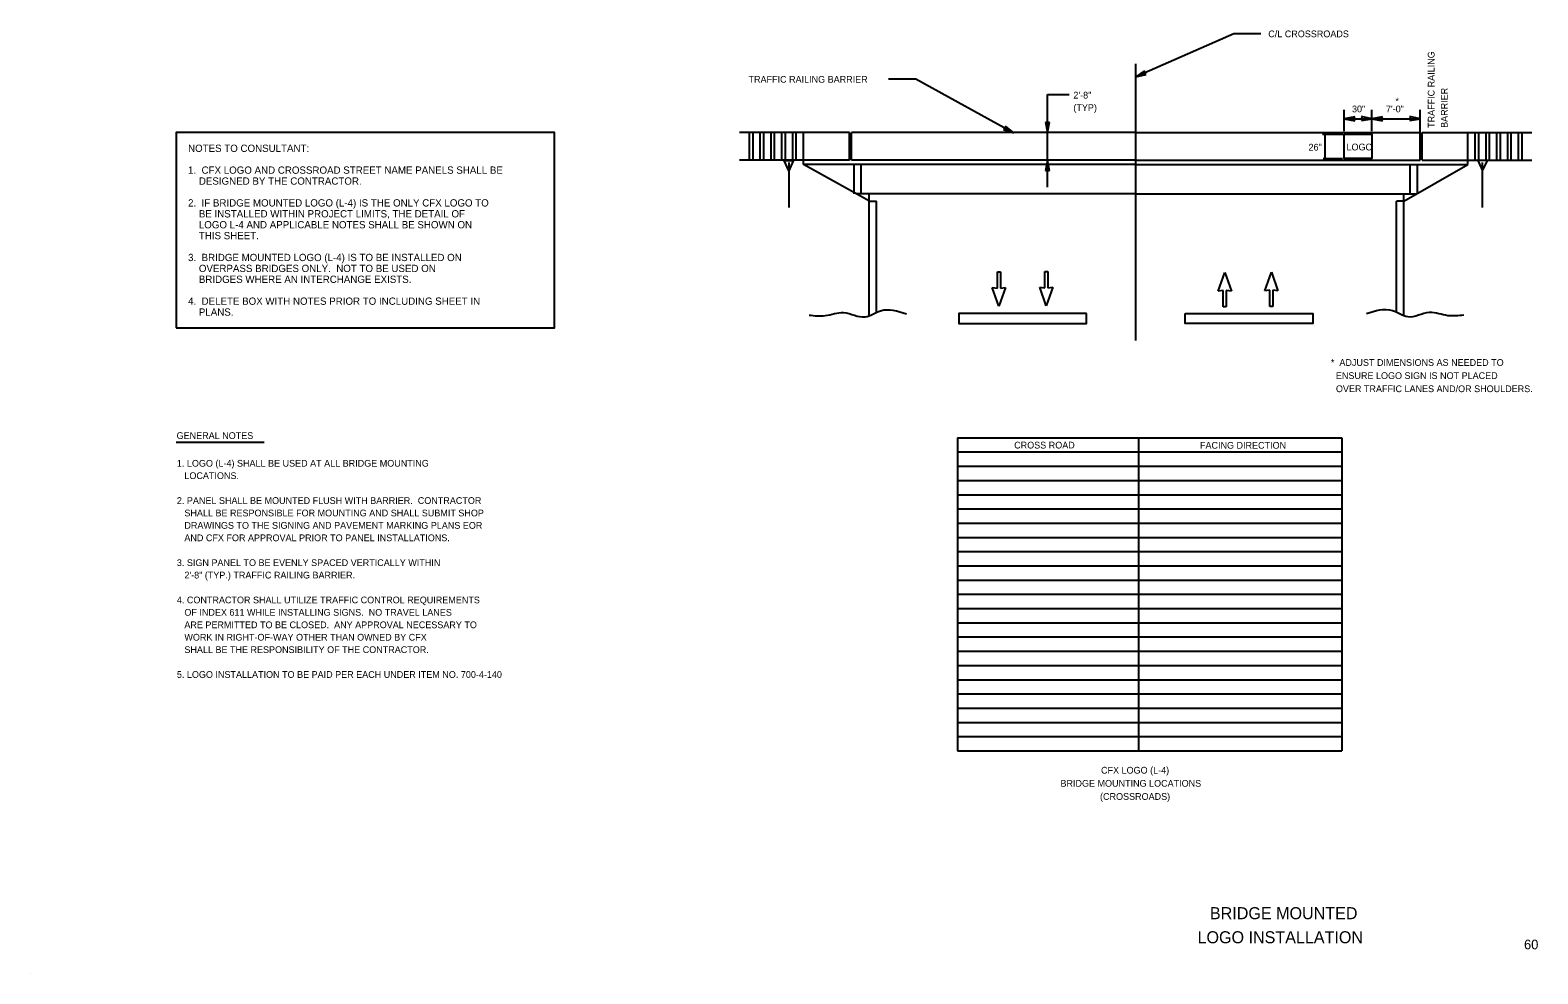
# Model space of a CAD drawing. Extents: x 53062 to 53689, y 9298 to 9690.
import ezdxf

# ---------------------------------------------------------------- set-up
doc = ezdxf.new("R2010")
doc.units = 0
for name, color, linetype in [('AdhocPoint_dp', 7, 'Continuous'), ('Bridge', 7, 'Continuous'), ('CLConst_dp', 7, 'Continuous'), ('Concrete', 7, 'Continuous'), ('DimLines_dp', 7, 'Continuous'), ('DirArrowsPavt', 7, 'Continuous'), ('Grass', 7, 'Continuous'), ('SignPanel', 7, 'Continuous'), ('TextAlert', 7, 'Continuous'), ('TextLabel', 7, 'Continuous'), ('TextMisc', 7, 'Continuous'), ('TextNotes', 7, 'Continuous'), ('TextShtNo', 7, 'Continuous'), ('TextTables', 7, 'Continuous')]:
    doc.layers.add(name, color=color, linetype=linetype)

msp = doc.modelspace()

# ---------------------------------------------------------------- linework, layer by layer
at = {"layer": 'AdhocPoint_dp'}
msp.add_line((53062.39, 9298.05), (53062.39, 9298.05), dxfattribs=at)
at = {"layer": 'Bridge'}
for p, q in [((53402.74, 9647.53), (53357.08, 9647.53)), ((53361.17, 9636.03), (53361.17, 9647.53)), ((53362.67, 9636.03), (53362.67, 9647.53)), ((53365.67, 9636.03), (53365.67, 9647.53)), ((53367.17, 9636.03), (53367.17, 9647.53)), ((53370.17, 9636.03), (53370.17, 9647.53)), ((53371.67, 9636.03), (53371.67, 9647.53)), ((53374.67, 9636.03), (53374.67, 9647.53)), ((53376.17, 9636.03), (53376.17, 9647.53)), ((53379.17, 9636.03), (53379.17, 9647.53)), ((53380.67, 9636.03), (53380.67, 9647.53)), ((53383.67, 9634.25), (53383.67, 9647.53)), ((53402.74, 9636.03), (53402.74, 9647.53)), ((53403.52, 9636.03), (53403.52, 9647.53)), ((53521.67, 9647.53), (53403.52, 9647.53)), ((53521.67, 9647.53), (53639.83, 9647.53)), ((53639.83, 9636.03), (53639.83, 9647.53)), ((53640.6, 9636.03), (53640.6, 9647.53)), ((53640.6, 9647.53), (53686.26, 9647.53)), ((53659.67, 9634.25), (53659.67, 9647.53)), ((53662.67, 9636.03), (53662.67, 9647.53)), ((53664.17, 9636.03), (53664.17, 9647.53)), ((53667.17, 9636.03), (53667.17, 9647.53)), ((53668.67, 9636.03), (53668.67, 9647.53)), ((53671.67, 9636.03), (53671.67, 9647.53)), ((53673.17, 9636.03), (53673.17, 9647.53)), ((53676.17, 9636.03), (53676.17, 9647.53)), ((53677.67, 9636.03), (53677.67, 9647.53)), ((53680.67, 9636.03), (53680.67, 9647.53)), ((53682.17, 9636.03), (53682.17, 9647.53)), ((53402.74, 9636.03), (53357.08, 9636.03)), ((53377.61, 9631.66), (53375.56, 9636.01)), ((53375.56, 9636.01), (53379.15, 9636.01)), ((53379.41, 9635.76), (53377.61, 9631.66)), ((53377.63, 9616.47), (53377.63, 9635.17)), ((53379.15, 9636.01), (53379.41, 9635.76)), ((53411, 9619.07), (53383.67, 9634.25)), ((53484.95, 9634.25), (53383.67, 9634.25)), ((53521.67, 9636.03), (53403.52, 9636.03)), ((53404.67, 9622.08), (53404.67, 9634.25)), ((53407.67, 9622.08), (53407.67, 9634.25)), ((53521.67, 9634.25), (53485.02, 9634.25)), ((53521.67, 9636.03), (53639.83, 9636.03)), ((53521.67, 9634.25), (53659.67, 9634.25)), ((53632.99, 9619.07), (53659.67, 9634.25)), ((53635.67, 9622.08), (53635.67, 9634.25)), ((53638.67, 9622.3), (53638.67, 9634.25)), ((53640.6, 9636.03), (53686.26, 9636.03)), ((53664.19, 9635.98), (53663.93, 9635.73)), ((53663.93, 9635.73), (53665.72, 9631.63)), ((53667.77, 9635.98), (53664.19, 9635.98)), ((53665.72, 9631.63), (53667.77, 9635.98)), ((53665.72, 9616.47), (53665.72, 9635.17)), ((53521.99, 9622.08), (53405.58, 9622.08)), ((53410.99, 9571.37), (53410.99, 9622.08)), ((53521.99, 9622.08), (53638.28, 9622.08)), ((53632.99, 9619.08), (53632.99, 9622.08)), ((53411, 9619.07), (53413.99, 9619.08)), ((53413.99, 9573.1), (53413.99, 9619.08)), ((53629.99, 9573.36), (53629.99, 9619.08)), ((53632.99, 9619.07), (53629.99, 9619.08)), ((53632.99, 9571.63), (53632.99, 9619.08))]:
    msp.add_line(p, q, dxfattribs=at)
at = {"layer": 'CLConst_dp'}
msp.add_line((53521.67, 9561.12), (53521.67, 9676.08), dxfattribs=at)
at = {"layer": 'Concrete'}
for points in [[(53501.23, 9572.38), (53448.21, 9572.38), (53448.21, 9568.28), (53501.23, 9568.28)], [(53542.25, 9572.38), (53595.27, 9572.38), (53595.27, 9568.28), (53542.25, 9568.28)]]:
    msp.add_lwpolyline(points, close=True, dxfattribs=at)
at = {"layer": 'DimLines_dp'}
for p, q in [((53484.98, 9663.31), (53494.03, 9663.31)), ((53484.98, 9647.58), (53484.98, 9663.31)), ((53484.98, 9651.6), (53484.17, 9651.93)), ((53484.17, 9651.93), (53484.98, 9647.58)), ((53484.98, 9651.6), (53484.17, 9651.93)), ((53484.17, 9651.93), (53484.98, 9647.58)), ((53484.98, 9647.58), (53485.82, 9651.93)), ((53485.82, 9651.93), (53484.98, 9651.6)), ((53484.98, 9647.58), (53485.82, 9651.93)), ((53485.82, 9651.93), (53484.98, 9651.6)), ((53608.28, 9648.18), (53608.28, 9657.05)), ((53612.63, 9654.12), (53608.28, 9653.32)), ((53612.63, 9654.12), (53608.28, 9653.32)), ((53608.28, 9653.32), (53619.79, 9653.32)), ((53608.28, 9653.32), (53612.63, 9652.48)), ((53608.28, 9653.32), (53612.63, 9652.48)), ((53612.3, 9653.32), (53612.63, 9654.12)), ((53612.3, 9653.32), (53612.63, 9654.12)), ((53612.63, 9652.48), (53612.3, 9653.32)), ((53612.63, 9652.48), (53612.3, 9653.32)), ((53619.79, 9653.32), (53615.44, 9654.16)), ((53615.44, 9654.16), (53615.77, 9653.32)), ((53619.79, 9653.32), (53615.44, 9654.16)), ((53615.44, 9654.16), (53615.77, 9653.32)), ((53615.77, 9653.32), (53615.44, 9652.51)), ((53615.44, 9652.51), (53619.79, 9653.32)), ((53615.77, 9653.32), (53615.44, 9652.51)), ((53615.44, 9652.51), (53619.79, 9653.32)), ((53619.79, 9648.18), (53619.79, 9657.05)), ((53624.14, 9654.12), (53619.79, 9653.32)), ((53624.14, 9654.12), (53619.79, 9653.32)), ((53619.79, 9653.32), (53639.83, 9653.32)), ((53619.79, 9653.32), (53624.14, 9652.48)), ((53619.79, 9653.32), (53624.14, 9652.48)), ((53623.81, 9653.32), (53624.14, 9654.12)), ((53623.81, 9653.32), (53624.14, 9654.12)), ((53624.14, 9652.48), (53623.81, 9653.32)), ((53624.14, 9652.48), (53623.81, 9653.32)), ((53639.83, 9653.32), (53635.48, 9654.16)), ((53635.48, 9654.16), (53635.81, 9653.32)), ((53635.81, 9653.32), (53635.48, 9652.51)), ((53635.48, 9652.51), (53639.83, 9653.32)), ((53639.83, 9647.53), (53639.83, 9657.05)), ((53484.98, 9634.25), (53484.98, 9647.58)), ((53599.29, 9646.83), (53607.63, 9646.83)), ((53600.31, 9636.49), (53600.31, 9646.94)), ((53484.98, 9636.03), (53484.14, 9631.68)), ((53484.98, 9624.91), (53484.98, 9636.03)), ((53485.79, 9631.68), (53484.98, 9636.03)), ((53599.49, 9636.75), (53607.58, 9636.75)), ((53484.14, 9631.68), (53484.98, 9632.01)), ((53484.98, 9632.01), (53485.79, 9631.68))]:
    msp.add_line(p, q, dxfattribs=at)
at = {"layer": 'DirArrowsPavt'}
for p, q in [((53464.18, 9589.7), (53465.42, 9589.7)), ((53464.18, 9582.95), (53464.18, 9589.7)), ((53465.42, 9589.7), (53465.42, 9582.95)), ((53483.9, 9589.83), (53485.15, 9589.83)), ((53483.9, 9583.08), (53483.9, 9589.83)), ((53485.15, 9589.83), (53485.15, 9583.08)), ((53555.92, 9581.69), (53558.66, 9589.42)), ((53558.66, 9589.42), (53561.41, 9581.69)), ((53575.25, 9581.82), (53578, 9589.55)), ((53578, 9589.55), (53580.75, 9581.82)), ((53464.8, 9575.45), (53462.05, 9583.18)), ((53462.05, 9583.18), (53464.18, 9582.95)), ((53467.55, 9583.18), (53464.8, 9575.45)), ((53465.42, 9582.95), (53467.55, 9583.18)), ((53484.52, 9575.58), (53481.77, 9583.31)), ((53481.77, 9583.31), (53483.9, 9583.08)), ((53487.27, 9583.31), (53484.52, 9575.58)), ((53485.15, 9583.08), (53487.27, 9583.31)), ((53558.04, 9581.92), (53555.92, 9581.69)), ((53558.04, 9575.17), (53558.04, 9581.92)), ((53561.41, 9581.69), (53559.29, 9581.92)), ((53559.29, 9581.92), (53559.29, 9575.17)), ((53577.38, 9582.05), (53575.25, 9581.82)), ((53577.38, 9575.3), (53577.38, 9582.05)), ((53580.75, 9581.82), (53578.63, 9582.05)), ((53578.63, 9582.05), (53578.63, 9575.3)), ((53559.29, 9575.17), (53558.04, 9575.17)), ((53578.63, 9575.3), (53577.38, 9575.3))]:
    msp.add_line(p, q, dxfattribs=at)
at = {"layer": 'Grass'}
for points in [[(53426.44, 9572.12), (53415.68, 9573.4), (53409.28, 9570.84), (53400.31, 9572.64), (53392.63, 9571.35), (53385.97, 9571.61)], [(53617.55, 9572.38), (53628.31, 9573.66), (53634.71, 9571.09), (53643.68, 9572.89), (53651.36, 9571.61), (53658.02, 9571.86)]]:
    msp.add_spline(points, degree=3, dxfattribs=at)
at = {"layer": 'SignPanel'}
msp.add_lwpolyline([(53608.28, 9646.83), (53619.78, 9646.83), (53619.78, 9636.75), (53608.28, 9636.75)], close=True, dxfattribs=at)
at = {"layer": 'TextAlert'}
msp.add_lwpolyline([(53122.98, 9566.47), (53280.25, 9566.47), (53280.25, 9647.53), (53122.98, 9647.53)], close=True, dxfattribs=at)
at = {"layer": 'TextLabel'}
for p, q in [((53562.43, 9688.6), (53521.67, 9670.67)), ((53573.7, 9688.6), (53562.43, 9688.6)), ((53525.33, 9673.17), (53521.67, 9670.67)), ((53521.67, 9670.67), (53525.99, 9671.66)), ((53525.35, 9672.29), (53525.33, 9673.17)), ((53525.99, 9671.66), (53525.35, 9672.29)), ((53418.98, 9669.81), (53430.25, 9669.81)), ((53430.25, 9669.81), (53471, 9647.4)), ((53467.48, 9649.34), (53466.8, 9648.79)), ((53467.48, 9649.34), (53466.8, 9648.79)), ((53466.8, 9648.79), (53471, 9647.4)), ((53466.8, 9648.79), (53471, 9647.4)), ((53467.6, 9650.23), (53467.48, 9649.34)), ((53467.6, 9650.23), (53467.48, 9649.34)), ((53471, 9647.4), (53467.6, 9650.23)), ((53471, 9647.4), (53467.6, 9650.23))]:
    msp.add_line(p, q, dxfattribs=at)
at = {"layer": 'TextNotes'}
msp.add_line((53122.98, 9518.92), (53159.57, 9518.92), dxfattribs=at)
at = {"layer": 'TextTables'}
for p, q in [((53447.62, 9520.76), (53607.31, 9520.76)), ((53447.62, 9520.76), (53447.62, 9390.7)), ((53522.91, 9390.7), (53522.91, 9520.76)), ((53607.31, 9520.76), (53607.31, 9390.7)), ((53447.62, 9514.85), (53607.31, 9514.85)), ((53447.62, 9508.94), (53607.31, 9508.94)), ((53447.62, 9503.03), (53607.31, 9503.03)), ((53447.62, 9497.11), (53607.31, 9497.11)), ((53447.63, 9491.2), (53607.31, 9491.2)), ((53447.62, 9485.29), (53607.31, 9485.29)), ((53447.62, 9479.38), (53607.31, 9479.38)), ((53447.62, 9473.47), (53607.31, 9473.47)), ((53447.62, 9467.56), (53607.31, 9467.56)), ((53447.62, 9461.64), (53607.31, 9461.64)), ((53447.62, 9455.73), (53607.31, 9455.73)), ((53447.62, 9449.82), (53607.31, 9449.82)), ((53447.62, 9443.91), (53607.31, 9443.91)), ((53447.62, 9437.99), (53607.31, 9437.99)), ((53447.62, 9432.08), (53607.31, 9432.08)), ((53447.62, 9426.17), (53607.31, 9426.17)), ((53447.62, 9420.26), (53607.31, 9420.26)), ((53447.62, 9414.35), (53607.31, 9414.35)), ((53447.62, 9408.43), (53607.31, 9408.43)), ((53447.62, 9402.52), (53607.31, 9402.52)), ((53447.62, 9396.61), (53607.31, 9396.61)), ((53447.62, 9390.7), (53607.31, 9390.7))]:
    msp.add_line(p, q, dxfattribs=at)

# ---------------------------------------------------------------- texts
at = {"layer": 'DimLines_dp'}
for s, p in [('2\'-8"', (53495.76, 9661.68)), ('(TYP)', (53495.76, 9656.51)), ('30"', (53611.5, 9655.96)), ('7\'-0"', (53625.6, 9655.95)), ('*', (53629.53, 9659.27)), ('26"', (53593.45, 9640.07))]:
    msp.add_text(s, height=2.8, dxfattribs=at).set_placement(p)
at = {"layer": 'TextAlert'}
for s, p in [('NOTES TO CONSULTANT:', (53127.98, 9639.51)), ('1.  CFX LOGO AND CROSSROAD STREET NAME PANELS SHALL BE', (53127.98, 9630.44)), ('    DESIGNED BY THE CONTRACTOR.', (53127.98, 9625.9)), ('2.  IF BRIDGE MOUNTED LOGO (L-4) IS THE ONLY CFX LOGO TO', (53127.98, 9616.83)), ('    BE INSTALLED WITHIN PROJECT LIMITS, THE DETAIL OF', (53127.98, 9612.29)), ('    LOGO L-4 AND APPLICABLE NOTES SHALL BE SHOWN ON', (53127.98, 9607.76)), ('    THIS SHEET.', (53127.98, 9603.22)), ('3.  BRIDGE MOUNTED LOGO (L-4) IS TO BE INSTALLED ON', (53127.98, 9594.15)), ('    OVERPASS BRIDGES ONLY.  NOT TO BE USED ON', (53127.98, 9589.61)), ('    BRIDGES WHERE AN INTERCHANGE EXISTS.', (53127.98, 9585.08)), ('4.  DELETE BOX WITH NOTES PRIOR TO INCLUDING SHEET IN', (53127.98, 9576)), ('    PLANS.', (53127.98, 9571.47))]:
    msp.add_text(s, height=3.024, dxfattribs=at).set_placement(p)
at = {"layer": 'TextLabel'}
for s, p in [('C/L CROSSROADS', (53576.71, 9687.15)), ('TRAFFIC RAILING BARRIER', (53360.81, 9668.26)), ('LOGO ', (53609.21, 9640.13))]:
    msp.add_text(s, height=2.8, dxfattribs=at).set_placement(p)
for s, p in [('TRAFFIC RAILING ', (53645.79, 9649.49)), ('BARRIER', (53651.25, 9649.49))]:
    msp.add_text(s, height=2.8, rotation=90, dxfattribs=at).set_placement(p)
at = {"layer": 'TextMisc'}
for s, p in [('     BRIDGE MOUNTED     ', (53543.2, 9320.75)), ('   LOGO INSTALLATION    ', (53541.77, 9310.75))]:
    msp.add_text(s, height=5, rotation=360, dxfattribs=at).set_placement(p)
at = {"layer": 'TextNotes'}
for s, p in [('*  ADJUST DIMENSIONS AS NEEDED TO', (53602.74, 9550.62)), ('  ENSURE LOGO SIGN IS NOT PLACED', (53602.74, 9545.17)), ('  OVER TRAFFIC LANES AND/OR SHOULDERS.', (53602.74, 9539.71)), ('GENERAL NOTES', (53123.23, 9520.26)), ('1. LOGO (L-4) SHALL BE USED AT ALL BRIDGE MOUNTING', (53123.34, 9508.76)), ('   LOCATIONS.', (53123.34, 9503.6)), ('2. PANEL SHALL BE MOUNTED FLUSH WITH BARRIER.  CONTRACTOR', (53123.34, 9493.27)), ('   SHALL BE RESPONSIBLE FOR MOUNTING AND SHALL SUBMIT SHOP', (53123.34, 9488.11)), ('   DRAWINGS TO THE SIGNING AND PAVEMENT MARKING PLANS EOR', (53123.34, 9482.95)), ('   AND CFX FOR APPROVAL PRIOR TO PANEL INSTALLATIONS.', (53123.34, 9477.79)), ('3. SIGN PANEL TO BE EVENLY SPACED VERTICALLY WITHIN ', (53123.34, 9467.46)), ('   2\'-8" (TYP.) TRAFFIC RAILING BARRIER.', (53123.34, 9462.3)), ('4. CONTRACTOR SHALL UTILIZE TRAFFIC CONTROL REQUIREMENTS', (53123.34, 9451.98)), ('   OF INDEX 611 WHILE INSTALLING SIGNS.  NO TRAVEL LANES ', (53123.34, 9446.82)), ('   ARE PERMITTED TO BE CLOSED.  ANY APPROVAL NECESSARY TO ', (53123.34, 9441.65)), ('   WORK IN RIGHT-OF-WAY OTHER THAN OWNED BY CFX', (53123.34, 9436.49)), ('   SHALL BE THE RESPONSIBILITY OF THE CONTRACTOR.', (53123.34, 9431.33)), ('5. LOGO INSTALLATION TO BE PAID PER EACH UNDER ITEM NO. 700-4-140', (53123.34, 9421.01))]:
    msp.add_text(s, height=2.8, dxfattribs=at).set_placement(p)
at = {"layer": 'TextShtNo'}
msp.add_text('60', height=4, rotation=360, dxfattribs=at).set_placement((53682.97, 9308.25))
at = {"layer": 'TextTables'}
for s, p in [('CROSS ROAD', (53471.16, 9516.3)), ('FACING DIRECTION', (53548.35, 9516.22)), ('CFX LOGO (L-4)', (53507.25, 9381.24)), ('BRIDGE MOUNTING LOCATIONS ', (53490.39, 9375.79)), ('(CROSSROADS)', (53506.83, 9370.33))]:
    msp.add_text(s, height=2.8, dxfattribs=at).set_placement(p)

doc.saveas('drawing.dxf')
